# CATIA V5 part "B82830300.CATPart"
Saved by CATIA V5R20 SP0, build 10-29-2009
Part number: B82830300
Revision: 4
Definition: design
Nomenclature: B82830300
Source: made
Description: NOT SPECIFIED
Bounding box of the stored display mesh (mm): x -17.817 to 17.817, y -18 to 18, z 0 to 300
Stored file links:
  C:\Users\Raffaele\Desktop\3D X SITO CF\BOLEX\7-PILLAR REF 828\B82830300.CATPart
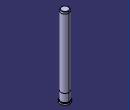
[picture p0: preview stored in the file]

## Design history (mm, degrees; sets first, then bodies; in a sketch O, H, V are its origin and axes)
Body1 "MANIFOLD_SOLID_BREP #450" (main body)
  Solid1: solid without history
